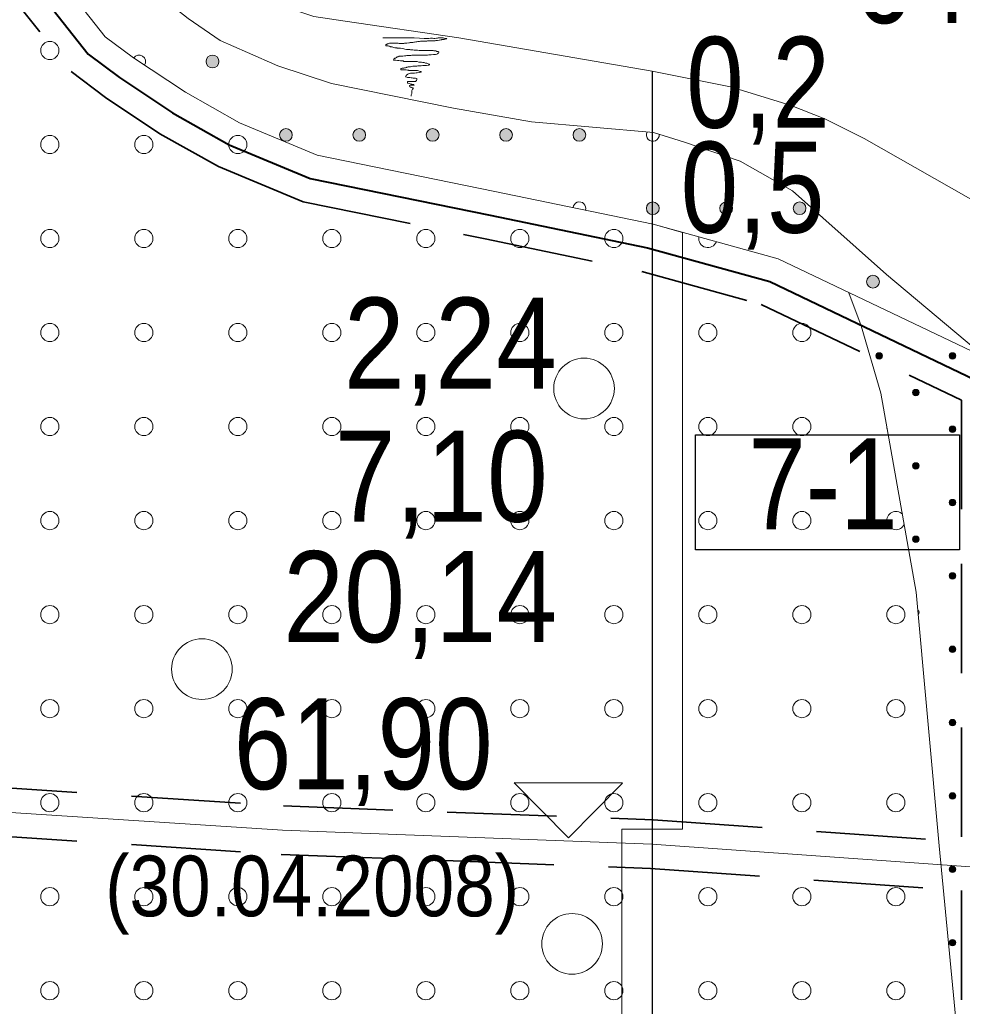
# Model space of a CAD drawing. Extents: x 640104 to 640970, y 6442278 to 6442689.
# Drawn here: x 640852.42 to 640883.5, y 6442532.6 to 6442565.13 of the extents above; entities that cross this region are included whole.
import ezdxf
from ezdxf.enums import TextEntityAlignment as Align

# ---------------------------------------------------------------- set-up
doc = ezdxf.new("R2010")
doc.units = 0
doc.header["$LTSCALE"] = 1.2
doc.linetypes.add('MEDIUM_DASHED', pattern=[4.5, 3, -1.5])
for name, color, linetype, lineweight in [('31', 7, 'Continuous', 13), ('32', 7, 'Continuous', 25), ('33', 7, 'Continuous', 13), ('34', 7, 'Continuous', 25), ('35', 7, 'Continuous', 35), ('40', 7, 'Continuous', 13), ('43', 7, 'Continuous', 13), ('45', 7, 'Continuous', 13), ('47', 7, 'Continuous', 13)]:
    doc.layers.add(name, color=color, linetype=linetype, lineweight=lineweight)

msp = doc.modelspace()

# ---------------------------------------------------------------- hatches: boundary and pattern name
at = {"layer": '45'}
for points in [[(640858.985, 6442563.755, 1), (640858.565, 6442563.755, 1)], [(640861.405, 6442561.335, 1), (640860.985, 6442561.335, 1)], [(640863.825, 6442561.335, 1), (640863.405, 6442561.335, 1)], [(640866.245, 6442561.335, 1), (640865.825, 6442561.335, 1)], [(640868.665, 6442561.335, 1), (640868.245, 6442561.335, 1)], [(640871.085, 6442561.335, 1), (640870.665, 6442561.335, 1)], [(640873.505, 6442558.915, 1), (640873.085, 6442558.915, 1)], [(640875.925, 6442558.915, 1), (640875.505, 6442558.915, 1)], [(640878.345, 6442558.915, 1), (640877.925, 6442558.915, 1)], [(640880.765, 6442556.495, 1), (640880.345, 6442556.495, 1)], [(640880.834, 6442554.123, 1), (640880.686, 6442553.974, 1)], [(640883.253, 6442554.123, 1), (640883.104, 6442553.974, 1)], [(640882.044, 6442552.914, 1), (640881.895, 6442552.765, 1)], [(640883.253, 6442551.705, 1), (640883.104, 6442551.556, 1)], [(640882.044, 6442550.495, 1), (640881.895, 6442550.347, 1)], [(640883.253, 6442549.286, 1), (640883.104, 6442549.138, 1)], [(640882.044, 6442548.077, 1), (640881.895, 6442547.929, 1)], [(640883.253, 6442546.868, 1), (640883.104, 6442546.719, 1)], [(640883.253, 6442544.45, 1), (640883.104, 6442544.301, 1)], [(640883.253, 6442542.031, 1), (640883.104, 6442541.883, 1)], [(640883.253, 6442539.613, 1), (640883.104, 6442539.465, 1)], [(640883.253, 6442537.195, 1), (640883.104, 6442537.046, 1)], [(640883.253, 6442534.776, 1), (640883.104, 6442534.628, 1)]]:
    msp.add_hatch(color=256, dxfattribs=at).paths.add_polyline_path(points)

# ---------------------------------------------------------------- linework, layer by layer
at = {"layer": '31'}
for points in [[(640795.09, 6442584.35), (640814.42, 6442583.6), (640821.25, 6442583.41), (640827.17, 6442582.76), (640831.24, 6442582), (640834.55, 6442580.89), (640839.22, 6442579.33), (640840.63, 6442578.96), (640843.45, 6442578.09), (640845.19, 6442577.33), (640846.17, 6442576.68), (640848.01, 6442574.94), (640849.55, 6442572.33), (640852.14, 6442568.5), (640855.23, 6442564.57), (640856.17, 6442563.88), (640857.88, 6442562.74), (640859.67, 6442561.73), (640862.23, 6442560.67), (640868.09, 6442559.47), (640873.31, 6442558.39), (640877.43, 6442557.25), (640884.28, 6442553.98)], [(640852.17, 6442577.61), (640853.2, 6442576.15), (640855, 6442571.07), (640855.94, 6442569.29), (640856.64, 6442568.45), (640858.08, 6442567.34), (640858.88, 6442566.71), (640859.94, 6442566.04), (640861.03, 6442565.6), (640862.12, 6442565.24), (640863.15, 6442565.08), (640866.9, 6442564.53), (640873.27, 6442563.44), (640875.86, 6442562.92), (640877.83, 6442562.32), (640878.97, 6442561.87), (640880.26, 6442561.22), (640884.27, 6442558.94), (640890.8, 6442555.81), (640895.27, 6442553.94), (640903.34, 6442551), (640905.53, 6442550.44), (640907.99, 6442550.17)], [(640850.57, 6442576.43), (640852.48, 6442573.28), (640853.64, 6442570.52), (640855.23, 6442567.85), (640856.75, 6442566.14), (640857.97, 6442565.17), (640859.03, 6442564.45), (640859.93, 6442564.05), (640860.93, 6442563.61), (640862.7, 6442563.03), (640866.72, 6442562.22), (640869.29, 6442561.77), (640873.32, 6442561.41), (640874.34, 6442561.1), (640876.18, 6442560.47), (640877.9, 6442559.49), (640881, 6442556.73), (640884.28, 6442553.98), (640888.13, 6442551.91), (640890.02, 6442551.1), (640891.92, 6442550.24), (640895.37, 6442548.86), (640901.98, 6442546.85), (640907.61, 6442545.9)], [(640879.76, 6442556.13), (640880.17, 6442555.04), (640880.81, 6442552.82), (640881.98, 6442546.26), (640882.74, 6442537.89), (640883.31, 6442531.94), (640883.88, 6442528.51), (640884.95, 6442523.51), (640887.12, 6442517.85), (640887.89, 6442516.13), (640889.37, 6442513.51), (640890.38, 6442512.35), (640891.79, 6442511.23), (640893.79, 6442509.72), (640895.27, 6442508.94)]]:
    msp.add_lwpolyline(points, dxfattribs=at)
at = {"layer": '32'}
msp.add_line((640873.27, 6442563.44), (640873.27, 6442503.44), dxfattribs=at)
at = {"layer": '33'}
for points in [[(640874.27, 6442538.44), (640874.27, 6442558.12), (640873.31, 6442558.39), (640873.27, 6442558.39), (640873.27, 6442538.44)], [(640872.27, 6442538.44), (640872.27, 6442509.66), (640873.2, 6442509.45), (640873.27, 6442509.45), (640873.27, 6442538.44)]]:
    msp.add_lwpolyline(points, close=True, dxfattribs=at)
at = {"layer": '33', "lineweight": 25}
msp.add_lwpolyline([(640874.7, 6442551.45), (640883.41, 6442551.45), (640883.41, 6442547.65), (640874.7, 6442547.65)], close=True, dxfattribs=at)
at = {"layer": '34', "lineweight": 13}
msp.add_lwpolyline([(640718.51, 6442547.61), (640760.64, 6442545.05), (640822.17, 6442540.94), (640861.08, 6442538.41), (640873.26, 6442537.95), (640895.2, 6442536.39), (640947.44, 6442534.5), (640955.05, 6442534.43)], dxfattribs=at)
at = {"layer": '34'}
msp.add_lwpolyline([(640868.72, 6442539.97), (640870.51, 6442538.16), (640872.29, 6442539.96)], close=True, dxfattribs=at)
at = {"layer": '35', "linetype": 'MEDIUM_DASHED'}
for p, q in [((640883.47, 6442552.59), (640883.47, 6442538.03)), ((640883.47, 6442536.42), (640883.47, 6442510.58))]:
    msp.add_line(p, q, dxfattribs=at)
at = {"layer": '35', "lineweight": 40}
msp.add_lwpolyline([(640795.06, 6442583.55), (640814.39, 6442582.8), (640821.2, 6442582.61), (640827.05, 6442581.97), (640831.04, 6442581.22), (640834.3, 6442580.13), (640838.99, 6442578.56), (640840.41, 6442578.19), (640843.17, 6442577.34), (640844.8, 6442576.63), (640845.67, 6442576.05), (640847.38, 6442574.44), (640848.87, 6442571.9), (640851.49, 6442568.03), (640854.67, 6442564), (640855.71, 6442563.23), (640857.46, 6442562.06), (640859.32, 6442561.01), (640862, 6442559.9), (640867.93, 6442558.69), (640873.12, 6442557.61), (640877.15, 6442556.5), (640883.92, 6442553.26)], dxfattribs=at)
at = {"layer": '35', "linetype": 'MEDIUM_DASHED'}
for points in [[(640795.03, 6442582.75), (640814.36, 6442582), (640821.14, 6442581.81), (640826.93, 6442581.17), (640830.84, 6442580.45), (640834.04, 6442579.37), (640838.76, 6442577.8), (640840.19, 6442577.42), (640842.89, 6442576.59), (640844.42, 6442575.92), (640845.17, 6442575.42), (640846.75, 6442573.93), (640848.2, 6442571.48), (640850.85, 6442567.56), (640854.11, 6442563.42), (640855.25, 6442562.57), (640857.04, 6442561.37), (640858.97, 6442560.29), (640861.76, 6442559.13), (640867.77, 6442557.91), (640872.93, 6442556.83), (640876.87, 6442555.74), (640883.47, 6442552.59)], [(640823.77, 6442541.64), (640861.12, 6442539.21), (640873.31, 6442538.75), (640883.47, 6442538.03)], [(640823.77, 6442540.04), (640861.04, 6442537.61), (640873.22, 6442537.15), (640883.47, 6442536.42)]]:
    msp.add_lwpolyline(points, dxfattribs=at)
at = {"layer": '40'}
for points in [[(640864.39, 6442564.53), (640864.42, 6442564.53), (640864.48, 6442564.53), (640864.53, 6442564.53), (640864.54, 6442564.53), (640864.6, 6442564.53), (640864.67, 6442564.53), (640864.84, 6442564.53), (640864.93, 6442564.53), (640864.94, 6442564.53), (640864.96, 6442564.53), (640865, 6442564.53), (640865.04, 6442564.53), (640865.09, 6442564.53), (640865.14, 6442564.53), (640865.17, 6442564.53), (640865.21, 6442564.53), (640865.24, 6442564.53), (640865.28, 6442564.53), (640865.32, 6442564.53), (640865.35, 6442564.53), (640865.38, 6442564.53), (640865.43, 6442564.53), (640865.6, 6442564.52), (640865.75, 6442564.51), (640865.8, 6442564.51), (640865.83, 6442564.51), (640865.85, 6442564.51), (640865.87, 6442564.51), (640865.91, 6442564.51), (640865.96, 6442564.52), (640865.98, 6442564.52), (640866, 6442564.52), (640866.01, 6442564.52), (640866.03, 6442564.52), (640866.07, 6442564.51), (640866.08, 6442564.51), (640866.11, 6442564.51), (640866.16, 6442564.52), (640866.19, 6442564.52), (640866.22, 6442564.53), (640866.24, 6442564.53), (640866.28, 6442564.53), (640866.29, 6442564.54), (640866.32, 6442564.54), (640866.34, 6442564.54), (640866.36, 6442564.53), (640866.38, 6442564.53), (640866.4, 6442564.52), (640866.42, 6442564.52)], [(640865.16, 6442564.36), (640865.14, 6442564.36), (640865.11, 6442564.36), (640865.09, 6442564.35), (640865.08, 6442564.35), (640865.06, 6442564.35), (640865.03, 6442564.35), (640865.01, 6442564.35), (640864.99, 6442564.35), (640864.95, 6442564.35), (640864.93, 6442564.35), (640864.9, 6442564.36), (640864.88, 6442564.36), (640864.87, 6442564.36), (640864.85, 6442564.36), (640864.82, 6442564.36), (640864.8, 6442564.36), (640864.76, 6442564.36), (640864.75, 6442564.36), (640864.73, 6442564.36), (640864.7, 6442564.36), (640864.68, 6442564.36), (640864.66, 6442564.36), (640864.64, 6442564.36), (640864.61, 6442564.36), (640864.59, 6442564.35), (640864.57, 6442564.34), (640864.55, 6442564.34), (640864.53, 6442564.33), (640864.52, 6442564.33), (640864.51, 6442564.32), (640864.49, 6442564.31), (640864.49, 6442564.29), (640864.49, 6442564.27), (640864.54, 6442564.27), (640864.57, 6442564.27), (640864.59, 6442564.26), (640864.61, 6442564.26), (640864.63, 6442564.25), (640864.64, 6442564.24), (640864.67, 6442564.24), (640864.7, 6442564.24), (640864.72, 6442564.23), (640864.75, 6442564.22), (640864.79, 6442564.21), (640864.82, 6442564.21), (640864.85, 6442564.21), (640864.87, 6442564.2), (640864.91, 6442564.2), (640864.97, 6442564.19)], [(640866.42, 6442564.52), (640866.44, 6442564.51), (640866.46, 6442564.51), (640866.49, 6442564.51), (640866.5, 6442564.5), (640866.49, 6442564.5), (640866.49, 6442564.5), (640866.47, 6442564.5), (640866.45, 6442564.49), (640866.42, 6442564.48), (640866.4, 6442564.48), (640866.38, 6442564.48), (640866.36, 6442564.48), (640866.34, 6442564.48), (640866.33, 6442564.47), (640866.3, 6442564.47), (640866.26, 6442564.46), (640866.25, 6442564.46), (640866.19, 6442564.45), (640866.16, 6442564.45), (640866.14, 6442564.45), (640866.12, 6442564.44), (640866.1, 6442564.44), (640866.08, 6442564.44), (640866.05, 6442564.44), (640866.03, 6442564.44), (640865.98, 6442564.44), (640865.95, 6442564.44), (640865.91, 6442564.44), (640865.87, 6442564.44), (640865.84, 6442564.43), (640865.81, 6442564.43), (640865.78, 6442564.42), (640865.75, 6442564.42), (640865.67, 6442564.42), (640865.65, 6442564.42), (640865.63, 6442564.42), (640865.6, 6442564.41), (640865.55, 6442564.41), (640865.51, 6442564.4), (640865.48, 6442564.4), (640865.44, 6442564.39), (640865.41, 6442564.39), (640865.38, 6442564.38), (640865.35, 6442564.38), (640865.34, 6442564.38), (640865.32, 6442564.38), (640865.29, 6442564.38), (640865.27, 6442564.37), (640865.25, 6442564.37), (640865.18, 6442564.36), (640865.16, 6442564.36)], [(640865.57, 6442563.96), (640865.53, 6442563.96), (640865.5, 6442563.96), (640865.45, 6442563.96), (640865.42, 6442563.96), (640865.39, 6442563.96), (640865.35, 6442563.96), (640865.31, 6442563.95), (640865.22, 6442563.95), (640865.18, 6442563.95), (640865.15, 6442563.94), (640865.11, 6442563.94), (640865.05, 6442563.93), (640864.99, 6442563.93), (640864.96, 6442563.93), (640864.93, 6442563.93), (640864.92, 6442563.92), (640864.9, 6442563.91), (640864.88, 6442563.91), (640864.87, 6442563.91), (640864.85, 6442563.9), (640864.84, 6442563.89), (640864.81, 6442563.87), (640864.79, 6442563.86), (640864.78, 6442563.85), (640864.76, 6442563.84), (640864.76, 6442563.83), (640864.75, 6442563.82), (640864.74, 6442563.81), (640864.75, 6442563.8), (640864.77, 6442563.8), (640864.8, 6442563.8), (640864.82, 6442563.8), (640864.88, 6442563.79), (640864.92, 6442563.79), (640864.97, 6442563.78), (640865.03, 6442563.78), (640865.06, 6442563.78), (640865.09, 6442563.76), (640865.12, 6442563.76), (640865.2, 6442563.76), (640865.27, 6442563.76), (640865.32, 6442563.76), (640865.38, 6442563.75), (640865.45, 6442563.75), (640865.52, 6442563.75), (640865.58, 6442563.73), (640865.62, 6442563.73), (640865.67, 6442563.73), (640865.71, 6442563.72)], [(640864.97, 6442564.19), (640865.04, 6442564.18), (640865.09, 6442564.17), (640865.12, 6442564.16), (640865.17, 6442564.15), (640865.21, 6442564.15), (640865.25, 6442564.15), (640865.28, 6442564.15), (640865.3, 6442564.14), (640865.35, 6442564.14), (640865.38, 6442564.14), (640865.42, 6442564.13), (640865.46, 6442564.13), (640865.5, 6442564.13), (640865.54, 6442564.13), (640865.59, 6442564.12), (640865.62, 6442564.12), (640865.63, 6442564.12), (640865.67, 6442564.12), (640865.71, 6442564.12), (640865.75, 6442564.12), (640865.8, 6442564.12), (640865.84, 6442564.12), (640865.87, 6442564.12), (640865.91, 6442564.12), (640865.93, 6442564.12), (640865.96, 6442564.12), (640865.99, 6442564.12), (640866.02, 6442564.12), (640866.05, 6442564.12), (640866.07, 6442564.11), (640866.14, 6442564.11), (640866.17, 6442564.09), (640866.2, 6442564.08), (640866.22, 6442564.08), (640866.24, 6442564.07), (640866.24, 6442564.05), (640866.23, 6442564.03), (640866.22, 6442564.03), (640866.21, 6442564.02), (640866.2, 6442564.01), (640866.17, 6442564), (640866.13, 6442563.99), (640866.06, 6442563.99), (640865.99, 6442563.97), (640865.96, 6442563.97), (640865.91, 6442563.97), (640865.87, 6442563.96), (640865.82, 6442563.96), (640865.75, 6442563.96), (640865.66, 6442563.96), (640865.57, 6442563.96)], [(640865.71, 6442563.72), (640865.74, 6442563.72), (640865.76, 6442563.72), (640865.8, 6442563.7), (640865.84, 6442563.7), (640865.86, 6442563.69), (640865.89, 6442563.68), (640865.92, 6442563.67), (640865.93, 6442563.67), (640865.93, 6442563.64), (640865.92, 6442563.64), (640865.91, 6442563.63), (640865.89, 6442563.63), (640865.83, 6442563.62), (640865.8, 6442563.62), (640865.78, 6442563.62), (640865.75, 6442563.62), (640865.71, 6442563.62), (640865.66, 6442563.61), (640865.64, 6442563.61), (640865.62, 6442563.61), (640865.55, 6442563.61), (640865.51, 6442563.6), (640865.5, 6442563.6), (640865.47, 6442563.6), (640865.45, 6442563.6), (640865.42, 6442563.6), (640865.38, 6442563.6), (640865.34, 6442563.59), (640865.3, 6442563.58), (640865.27, 6442563.58), (640865.25, 6442563.58), (640865.23, 6442563.58), (640865.21, 6442563.57), (640865.18, 6442563.57), (640865.17, 6442563.56), (640865.14, 6442563.55), (640865.13, 6442563.55), (640865.11, 6442563.55), (640865.09, 6442563.54), (640865.06, 6442563.54), (640865.03, 6442563.53), (640865, 6442563.52), (640864.99, 6442563.51), (640864.99, 6442563.48), (640865.01, 6442563.48), (640865.05, 6442563.48), (640865.09, 6442563.48), (640865.14, 6442563.48), (640865.16, 6442563.48), (640865.21, 6442563.47), (640865.24, 6442563.47)], [(640865.24, 6442563.47), (640865.25, 6442563.46), (640865.27, 6442563.46), (640865.3, 6442563.46), (640865.33, 6442563.46), (640865.35, 6442563.46), (640865.41, 6442563.46), (640865.45, 6442563.46), (640865.47, 6442563.46), (640865.49, 6442563.46), (640865.51, 6442563.46), (640865.54, 6442563.46), (640865.57, 6442563.45), (640865.59, 6442563.44), (640865.62, 6442563.43), (640865.64, 6442563.43), (640865.66, 6442563.42), (640865.66, 6442563.4), (640865.6, 6442563.39), (640865.52, 6442563.38), (640865.49, 6442563.38), (640865.44, 6442563.37), (640865.41, 6442563.37), (640865.37, 6442563.37), (640865.33, 6442563.37), (640865.3, 6442563.37), (640865.26, 6442563.36), (640865.22, 6442563.34), (640865.21, 6442563.33), (640865.18, 6442563.31), (640865.17, 6442563.3), (640865.16, 6442563.29), (640865.15, 6442563.27), (640865.14, 6442563.25), (640865.15, 6442563.25), (640865.18, 6442563.24), (640865.21, 6442563.23), (640865.28, 6442563.23), (640865.33, 6442563.22), (640865.36, 6442563.22), (640865.39, 6442563.21), (640865.42, 6442563.21), (640865.47, 6442563.21), (640865.51, 6442563.19), (640865.51, 6442563.16), (640865.51, 6442563.15), (640865.5, 6442563.13), (640865.47, 6442563.1), (640865.45, 6442563.1), (640865.42, 6442563.1), (640865.38, 6442563.1), (640865.33, 6442563.1), (640865.3, 6442563.1), (640865.26, 6442563.1), (640865.21, 6442563.09), (640865.21, 6442563.07), (640865.2, 6442563.06), (640865.21, 6442563.04), (640865.23, 6442563.04), (640865.29, 6442563.02), (640865.33, 6442563.01), (640865.35, 6442563.01), (640865.38, 6442563), (640865.41, 6442563), (640865.43, 6442562.98), (640865.42, 6442562.98), (640865.39, 6442562.98), (640865.35, 6442562.97), (640865.3, 6442562.97), (640865.29, 6442562.97), (640865.27, 6442562.96), (640865.27, 6442562.94), (640865.28, 6442562.92), (640865.29, 6442562.92), (640865.31, 6442562.91), (640865.33, 6442562.9), (640865.36, 6442562.89), (640865.39, 6442562.89), (640865.39, 6442562.86), (640865.38, 6442562.85), (640865.38, 6442562.83), (640865.36, 6442562.82), (640865.35, 6442562.8), (640865.35, 6442562.78), (640865.35, 6442562.76), (640865.35, 6442562.74), (640865.35, 6442562.72), (640865.35, 6442562.7), (640865.34, 6442562.68), (640865.33, 6442562.66), (640865.33, 6442562.64), (640865.33, 6442562.62), (640865.33, 6442562.61), (640865.33, 6442562.63)]]:
    msp.add_lwpolyline(points, dxfattribs=at)
at = {"layer": '43'}
for centre in [(640853.411, 6442564.118), (640853.411, 6442561.018), (640856.511, 6442561.018), (640859.611, 6442561.018), (640853.411, 6442557.918), (640856.511, 6442557.918), (640859.611, 6442557.918), (640862.711, 6442557.918), (640865.811, 6442557.918), (640868.911, 6442557.918), (640872.011, 6442557.918), (640853.411, 6442554.818), (640856.511, 6442554.818), (640859.611, 6442554.818), (640862.711, 6442554.818), (640865.811, 6442554.818), (640868.911, 6442554.818), (640872.011, 6442554.818), (640875.111, 6442554.818), (640878.211, 6442554.818), (640853.411, 6442551.718), (640856.511, 6442551.718), (640859.611, 6442551.718), (640862.711, 6442551.718), (640865.811, 6442551.718), (640868.911, 6442551.718), (640872.011, 6442551.718), (640875.111, 6442551.718), (640878.211, 6442551.718), (640853.411, 6442548.618), (640856.511, 6442548.618), (640859.611, 6442548.618), (640862.711, 6442548.618), (640865.811, 6442548.618), (640868.911, 6442548.618), (640872.011, 6442548.618), (640875.111, 6442548.618), (640878.211, 6442548.618), (640853.411, 6442545.518), (640856.511, 6442545.518), (640859.611, 6442545.518), (640862.711, 6442545.518), (640865.811, 6442545.518), (640868.911, 6442545.518), (640872.011, 6442545.518), (640875.111, 6442545.518), (640878.211, 6442545.518), (640881.311, 6442545.518), (640853.411, 6442542.418), (640856.511, 6442542.418), (640859.611, 6442542.418), (640862.711, 6442542.418), (640865.811, 6442542.418), (640868.911, 6442542.418), (640872.011, 6442542.418), (640875.111, 6442542.418), (640878.211, 6442542.418), (640881.311, 6442542.418), (640853.411, 6442539.318), (640856.511, 6442539.318), (640859.611, 6442539.318), (640862.711, 6442539.318), (640865.811, 6442539.318), (640868.911, 6442539.318), (640872.011, 6442539.318), (640875.111, 6442539.318), (640878.211, 6442539.318), (640881.311, 6442539.318), (640853.411, 6442536.218), (640856.511, 6442536.218), (640859.611, 6442536.218), (640862.711, 6442536.218), (640865.811, 6442536.218), (640868.911, 6442536.218), (640872.011, 6442536.218), (640875.111, 6442536.218), (640878.211, 6442536.218), (640881.311, 6442536.218), (640853.411, 6442533.118), (640856.511, 6442533.118), (640859.611, 6442533.118), (640862.711, 6442533.118), (640865.811, 6442533.118), (640868.911, 6442533.118), (640872.011, 6442533.118), (640875.111, 6442533.118), (640878.211, 6442533.118), (640881.311, 6442533.118)]:
    msp.add_circle(centre, 0.3, dxfattribs=at)
for centre, start, end in [((640875.111, 6442557.918), 170.1096, 338.9978), ((640881.311, 6442551.718), 183.123, 197.1263), ((640881.311, 6442548.618), 44.6414, 335.6079)]:
    msp.add_arc(centre, 0.3, start, end, dxfattribs=at)
at = {"layer": '45'}
for centre, radius in [((640858.775, 6442563.755), 0.21), ((640861.195, 6442561.335), 0.21), ((640863.615, 6442561.335), 0.21), ((640866.035, 6442561.335), 0.21), ((640868.455, 6442561.335), 0.21), ((640870.875, 6442561.335), 0.21), ((640873.295, 6442558.915), 0.21), ((640875.715, 6442558.915), 0.21), ((640878.135, 6442558.915), 0.21), ((640880.555, 6442556.495), 0.21), ((640880.76, 6442554.049), 0.105), ((640883.178, 6442554.049), 0.105), ((640881.969, 6442552.839), 0.105), ((640883.178, 6442551.63), 0.105), ((640881.969, 6442550.421), 0.105), ((640883.178, 6442549.212), 0.105), ((640881.969, 6442548.003), 0.105), ((640883.178, 6442546.794), 0.105), ((640883.178, 6442544.375), 0.105), ((640883.178, 6442541.957), 0.105), ((640883.178, 6442539.539), 0.105), ((640883.178, 6442537.121), 0.105), ((640883.178, 6442534.702), 0.105)]:
    msp.add_circle(centre, radius, dxfattribs=at)
for centre, radius, start, end in [((640856.355, 6442563.755), 0.21, 326.5944, 145.8495), ((640873.295, 6442561.335), 0.21, 154.1617, 4.5135), ((640870.875, 6442558.915), 0.21, 342.3503, 174.1132), ((640881.969, 6442545.585), 0.105, 320.5953, 49.751)]:
    msp.add_arc(centre, radius, start, end, dxfattribs=at)
at = {"layer": '47'}
for centre in [(640871.027, 6442552.973), (640858.426, 6442543.719), (640870.633, 6442534.662)]:
    msp.add_circle(centre, 1, dxfattribs=at)

# ---------------------------------------------------------------- texts
at = {"layer": '32', "width": 0.85}
for s, p in [('64,00', (640884.205, 6442565.02)), ('0,2', (640876.765, 6442561.57)), ('0,5', (640876.585, 6442558.11))]:
    msp.add_text(s, height=3, dxfattribs=at).set_placement(p, align=Align.CENTER)
at = {"layer": '33'}
for s, width, p in [('2,24', 0.9, (640866.62, 6442552.97)), ('7,10', 0.9, (640866.32, 6442548.58)), ('7-1', 0.85, (640878.905, 6442548.33)), ('20,14', 0.9, (640865.625, 6442544.61))]:
    msp.add_text(s, height=3, dxfattribs=dict(at, width=width)).set_placement(p, align=Align.CENTER)
at = {"layer": '34'}
for s, height, width, p in [('61,90', 3, 0.85, (640863.745, 6442539.76)), ('(30.04.2008)', 2, 0.9, (640862.06, 6442535.57))]:
    msp.add_text(s, height=height, dxfattribs=dict(at, width=width)).set_placement(p, align=Align.CENTER)

doc.saveas('drawing.dxf')
